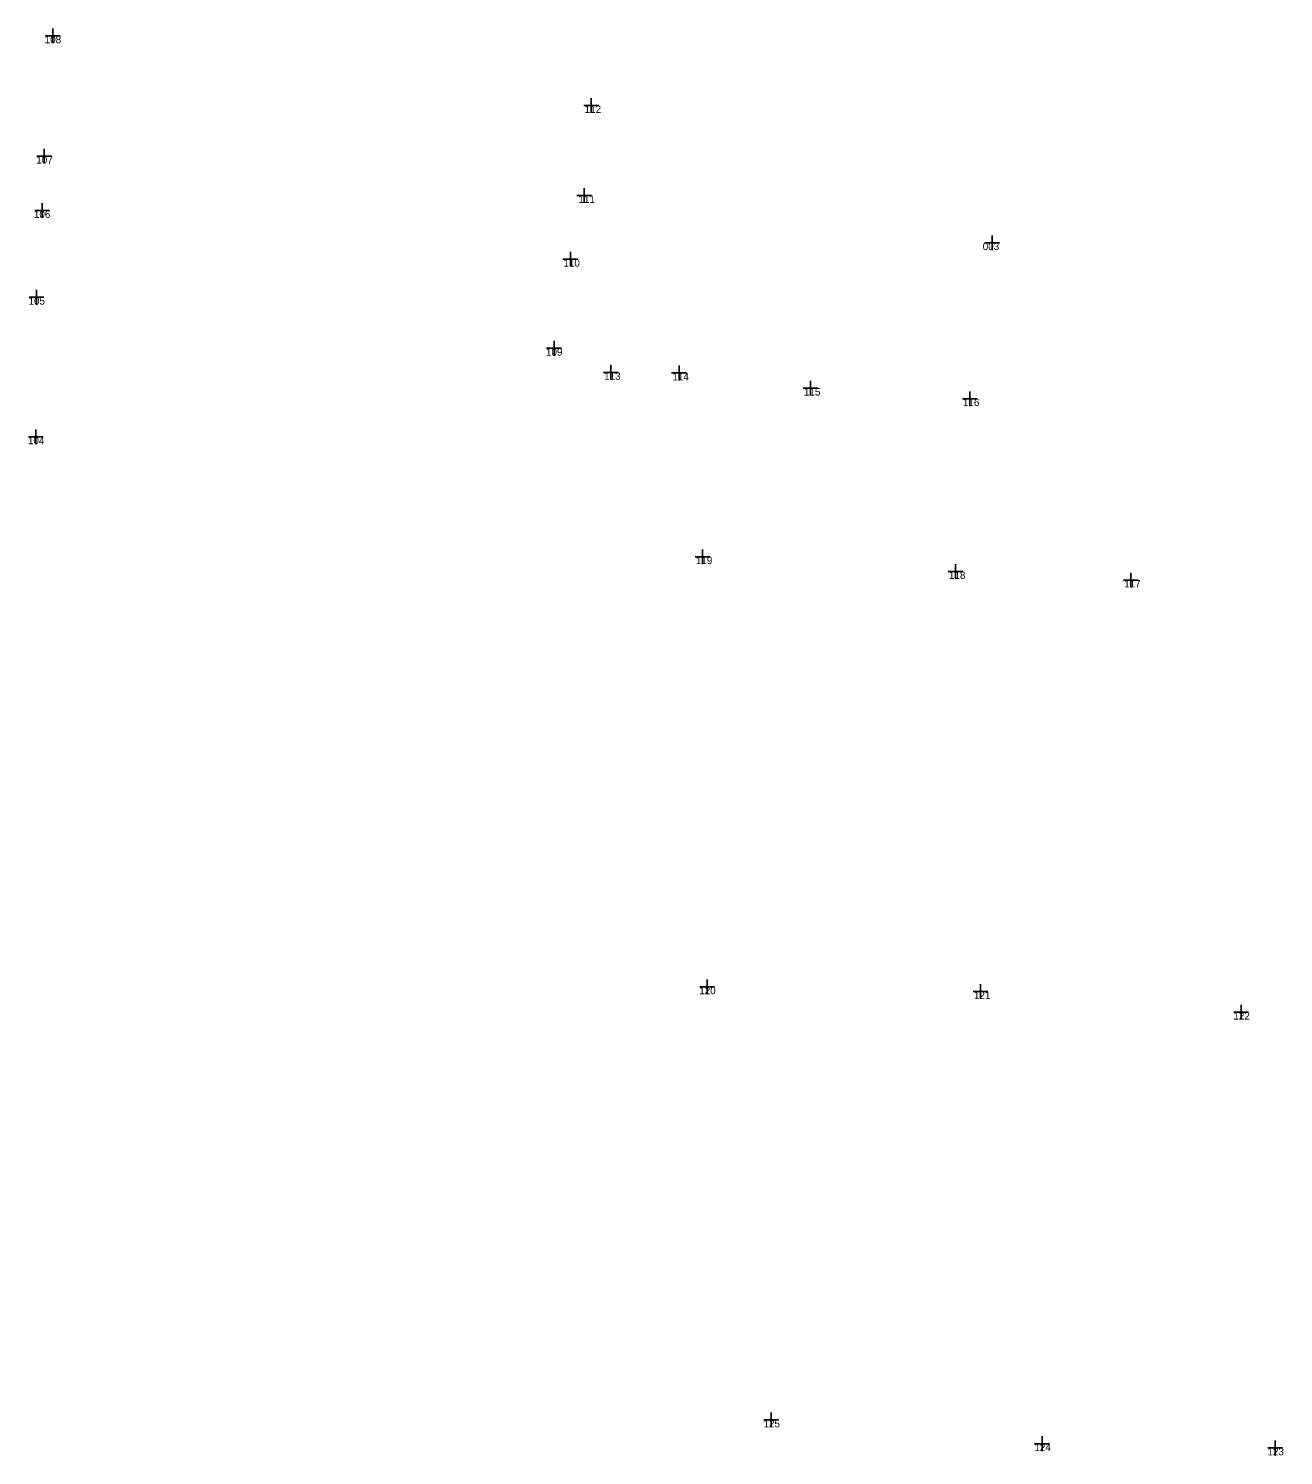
# Model space of a CAD drawing. Extents: x -706655 to -706193, y -1036183 to -1035040.
# Drawn here: x -706282.4 to -706197.3, y -1035600.4 to -1035503.7 of the extents above; entities that cross this region are included whole.
import ezdxf

# ---------------------------------------------------------------- set-up
doc = ezdxf.new("R2010")
doc.units = 0
doc.layers.add('čísla bodu', color=7, linetype='Continuous')

msp = doc.modelspace()

# ---------------------------------------------------------------- linework, layer by layer
at = {"layer": 'čísla bodu'}
for p, q in [((-706280.75, -1035504.65), (-706280.75, -1035503.65)), ((-706281.25, -1035504.15), (-706280.25, -1035504.15)), ((-706280.75, -1035504.15), (-706280.75, -1035504.15)), ((-706244.22, -1035509.37), (-706244.22, -1035508.37)), ((-706244.72, -1035508.87), (-706243.72, -1035508.87)), ((-706244.22, -1035508.87), (-706244.22, -1035508.87)), ((-706281.82, -1035512.3), (-706280.82, -1035512.3)), ((-706281.32, -1035512.8), (-706281.32, -1035511.8)), ((-706281.32, -1035512.3), (-706281.32, -1035512.3)), ((-706244.71, -1035515.47), (-706244.71, -1035514.47)), ((-706245.21, -1035514.97), (-706244.21, -1035514.97)), ((-706244.71, -1035514.97), (-706244.71, -1035514.97)), ((-706281.97, -1035515.99), (-706280.97, -1035515.99)), ((-706281.47, -1035516.49), (-706281.47, -1035515.49)), ((-706281.47, -1035515.99), (-706281.47, -1035515.99)), ((-706217.54, -1035518.17), (-706216.54, -1035518.17)), ((-706217.04, -1035518.67), (-706217.04, -1035517.67)), ((-706217.04, -1035518.17), (-706217.04, -1035518.17)), ((-706246.14, -1035519.29), (-706245.14, -1035519.29)), ((-706245.64, -1035519.79), (-706245.64, -1035518.79)), ((-706245.64, -1035519.29), (-706245.64, -1035519.29)), ((-706282.35, -1035521.87), (-706281.35, -1035521.87)), ((-706281.85, -1035522.37), (-706281.85, -1035521.37)), ((-706281.85, -1035521.87), (-706281.85, -1035521.87)), ((-706246.75, -1035525.83), (-706246.75, -1035524.83)), ((-706247.25, -1035525.33), (-706246.25, -1035525.33)), ((-706246.75, -1035525.33), (-706246.75, -1035525.33)), ((-706243.4, -1035526.96), (-706242.4, -1035526.96)), ((-706242.9, -1035527.46), (-706242.9, -1035526.46)), ((-706242.9, -1035526.96), (-706242.9, -1035526.96)), ((-706238.77, -1035527), (-706237.77, -1035527)), ((-706238.27, -1035527.5), (-706238.27, -1035526.5)), ((-706238.27, -1035527), (-706238.27, -1035527)), ((-706229.85, -1035528.03), (-706228.85, -1035528.03)), ((-706229.35, -1035528.53), (-706229.35, -1035527.53)), ((-706229.35, -1035528.03), (-706229.35, -1035528.03)), ((-706219.05, -1035528.75), (-706218.05, -1035528.75)), ((-706218.55, -1035529.25), (-706218.55, -1035528.25)), ((-706218.55, -1035528.75), (-706218.55, -1035528.75)), ((-706281.89, -1035531.83), (-706281.89, -1035530.83)), ((-706282.39, -1035531.33), (-706281.39, -1035531.33)), ((-706281.89, -1035531.33), (-706281.89, -1035531.33)), ((-706237.18, -1035539.46), (-706236.18, -1035539.46)), ((-706236.68, -1035539.96), (-706236.68, -1035538.96)), ((-706236.68, -1035539.46), (-706236.68, -1035539.46)), ((-706220.01, -1035540.46), (-706219.01, -1035540.46)), ((-706219.51, -1035540.96), (-706219.51, -1035539.96)), ((-706219.51, -1035540.46), (-706219.51, -1035540.46)), ((-706207.63, -1035541.54), (-706207.63, -1035540.54)), ((-706208.13, -1035541.04), (-706207.13, -1035541.04)), ((-706207.63, -1035541.04), (-706207.63, -1035541.04)), ((-706236.86, -1035568.62), (-706235.86, -1035568.62)), ((-706236.36, -1035569.12), (-706236.36, -1035568.12)), ((-706236.36, -1035568.62), (-706236.36, -1035568.62)), ((-706217.82, -1035569.44), (-706217.82, -1035568.44)), ((-706218.32, -1035568.94), (-706217.32, -1035568.94)), ((-706217.82, -1035568.94), (-706217.82, -1035568.94)), ((-706200.65, -1035570.34), (-706199.65, -1035570.34)), ((-706200.15, -1035570.84), (-706200.15, -1035569.84)), ((-706200.15, -1035570.34), (-706200.15, -1035570.34)), ((-706232.02, -1035598.48), (-706232.02, -1035597.48)), ((-706232.52, -1035597.98), (-706231.52, -1035597.98)), ((-706232.02, -1035597.98), (-706232.02, -1035597.98)), ((-706214.15, -1035599.59), (-706213.15, -1035599.59)), ((-706213.65, -1035600.09), (-706213.65, -1035599.09)), ((-706213.65, -1035599.59), (-706213.65, -1035599.59)), ((-706197.84, -1035600.38), (-706197.84, -1035599.38)), ((-706198.34, -1035599.88), (-706197.34, -1035599.88)), ((-706197.84, -1035599.88), (-706197.84, -1035599.88))]:
    msp.add_line(p, q, dxfattribs=at)

# ---------------------------------------------------------------- texts
for s, p in [('108', (-706281.291, -1035504.65)), ('112', (-706244.669, -1035509.37)), ('107', (-706281.861, -1035512.8)), ('111', (-706245.09, -1035515.47)), ('106', (-706282.025, -1035516.49)), ('003', (-706217.674, -1035518.67)), ('110', (-706246.11, -1035519.79)), ('105', (-706282.391, -1035522.37)), ('109', (-706247.293, -1035525.83)), ('113', (-706243.349, -1035527.46)), ('114', (-706238.719, -1035527.5)), ('115', (-706229.799, -1035528.53)), ('116', (-706219.012, -1035529.25)), ('104', (-706282.431, -1035531.83)), ('119', (-706237.131, -1035539.96)), ('118', (-706219.959, -1035540.96)), ('117', (-706208.079, -1035541.54)), ('120', (-706236.901, -1035569.12)), ('121', (-706218.27, -1035569.44)), ('122', (-706200.67, -1035570.84)), ('125', (-706232.54, -1035598.48)), ('124', (-706214.17, -1035600.09)), ('123', (-706198.36, -1035600.38))]:
    msp.add_text(s, height=0.5, dxfattribs=at).set_placement(p)

doc.saveas('drawing.dxf')
